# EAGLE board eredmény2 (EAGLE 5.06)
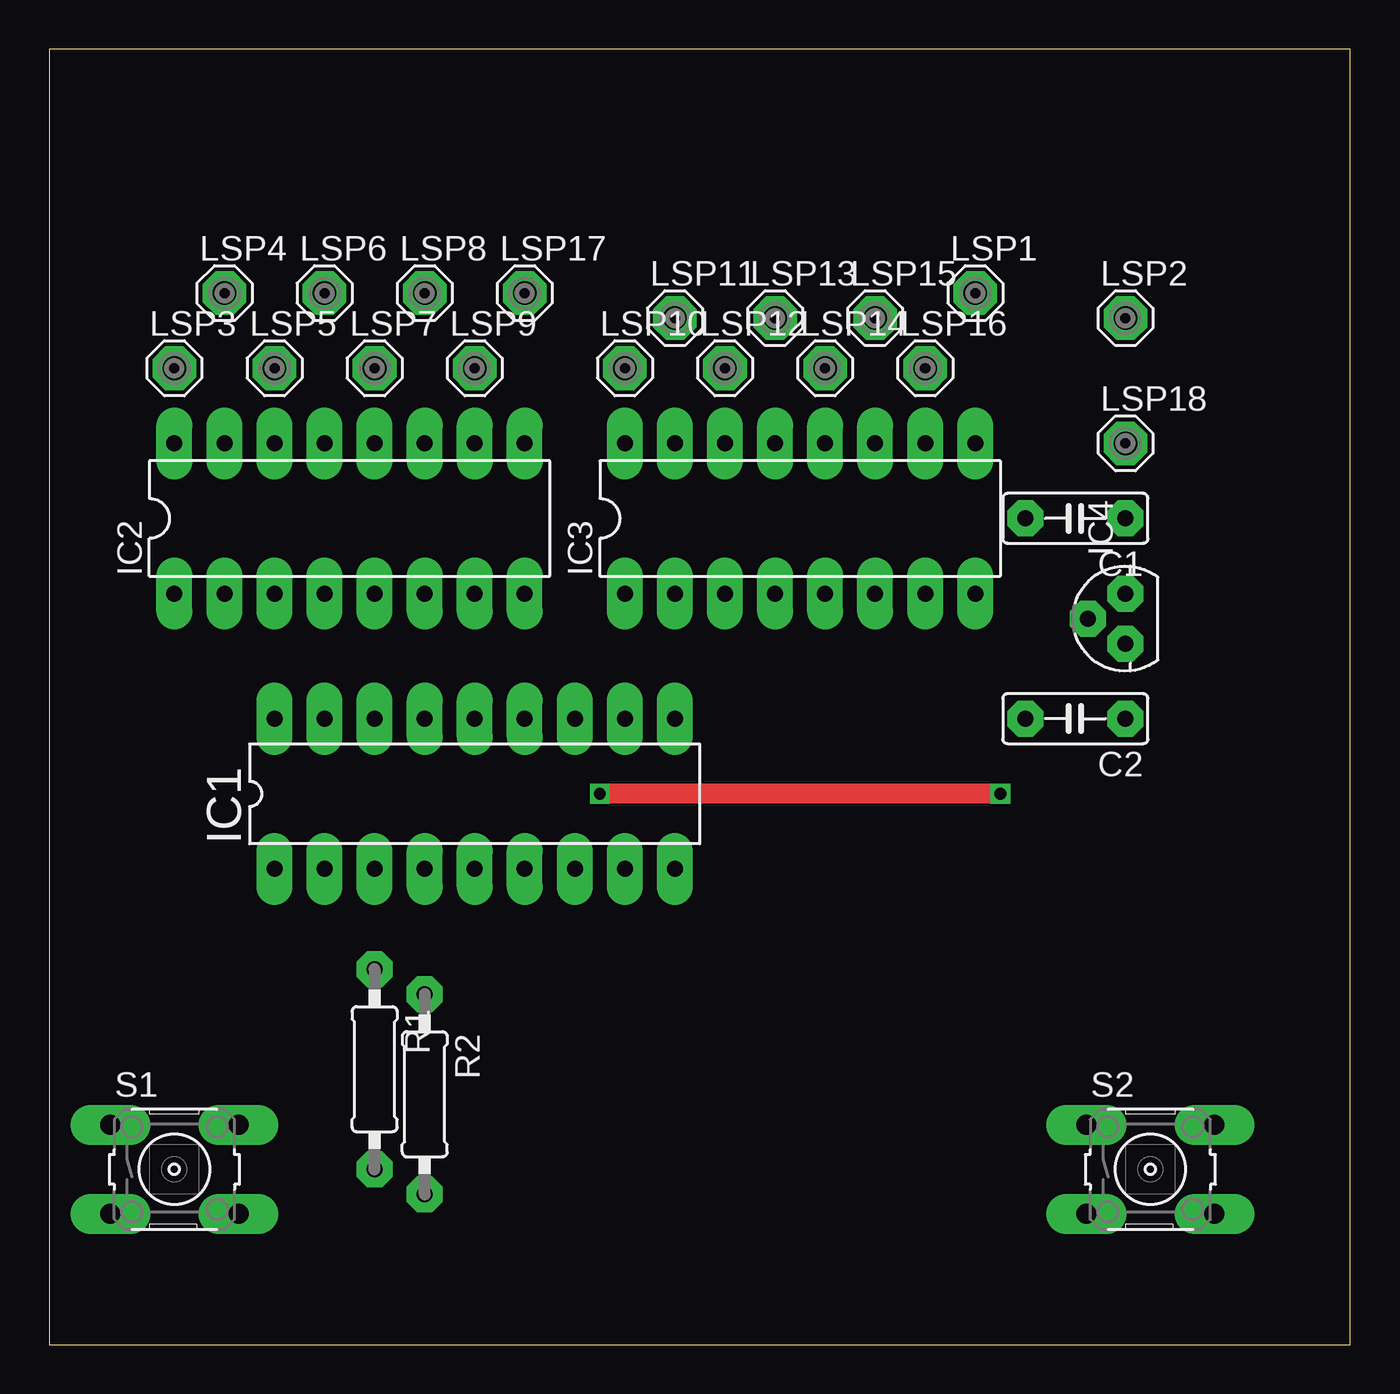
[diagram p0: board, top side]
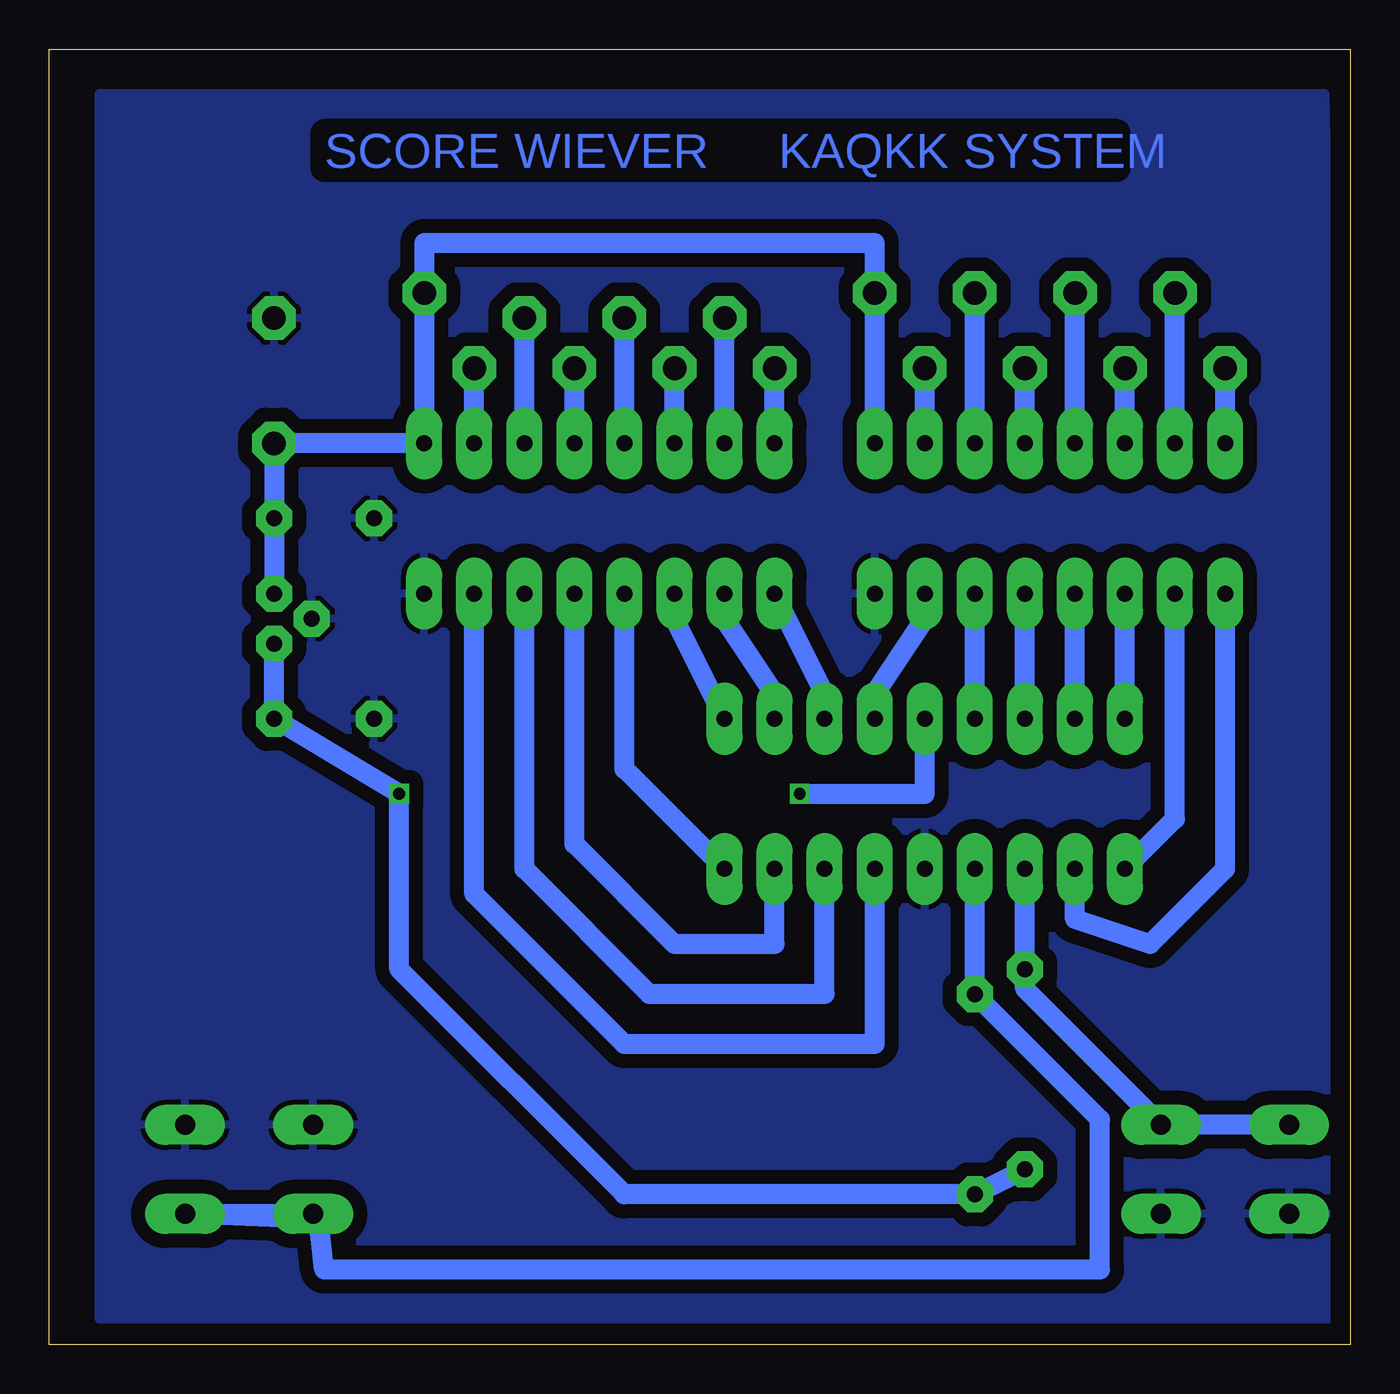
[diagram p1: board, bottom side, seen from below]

Size 66.02 x 65.71 mm. Coordinates in mm from the lower left corner, seen from the top.
Outline: 0,0 66.02,0 66.02,65.71 0,65.71 0,0
Copper layers (1*16): Top 0.035mm / dielectric 1.5mm / Bottom 0.035mm
Design rules "default *": minimum track width 10mil, minimum drill 24mil, track to track 28mil, track to pad 28mil, pad to pad 8mil, via to via 8mil, smd to smd 8mil, copper to edge 40mil, drill to drill 8mil, minimum pad ring 20mil, minimum via ring 8mil, stop-mask expansion 4mil, vias tented up to drill 0mil, thermal gap 10mil

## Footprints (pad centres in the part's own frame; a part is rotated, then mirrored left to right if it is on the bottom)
C050-025X075 = drill 0.813 octagon: 1 -2.54,0; 2 2.54,0
DIL18 = drill 0.813 long: 1 -10.16,-3.81; 2 -7.62,-3.81; 3 -5.08,-3.81; 4 -2.54,-3.81; 5 0,-3.81; 6 2.54,-3.81; 7 5.08,-3.81; 8 7.62,-3.81; 9 10.16,-3.81; 10 10.16,3.81; 11 7.62,3.81; 12 5.08,3.81; 13 2.54,3.81; 14 0,3.81; 15 -2.54,3.81; 16 -5.08,3.81; 17 -7.62,3.81; 18 -10.16,3.81
DIL16 = drill 0.813 long: 1 -8.89,-3.81; 2 -6.35,-3.81; 3 -3.81,-3.81; 4 -1.27,-3.81; 5 1.27,-3.81; 6 3.81,-3.81; 7 6.35,-3.81; 8 8.89,-3.81; 9 8.89,3.81; 10 6.35,3.81; 11 3.81,3.81; 12 1.27,3.81; 13 -1.27,3.81; 14 -3.81,3.81; 15 -6.35,3.81; 16 -8.89,3.81
78LXX = drill 0.813 octagon: GND 0,1.905; IN 1.27,0; OUT -1.27,0
MCS08 = drill 1.194 pad 2.159 octagon: MP 0,0
0207/10 = drill 0.813 octagon: 1 -5.08,0; 2 5.08,0
B3F-10XX = drill 1.016 long: 1 -3.251,2.261; 2 3.251,2.261; 3 -3.251,-2.261; 4 3.251,-2.261

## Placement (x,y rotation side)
C1  [C050-025X075]  52.07,41.91 180 top
C2  [C050-025X075]  52.07,31.75 180 top
IC1  PIC16F628P  [DIL18]  21.59,27.94 0 top
IC2  ULN2003AN  [DIL16]  15.24,41.91 0 top
IC3  ULN2003AN  [DIL16]  38.1,41.91 0 top
IC4  [78LXX]  54.61,36.83 90 top
LSP1  MCS08  [MCS08]  46.99,53.34 0 top
LSP2  MCS08  [MCS08]  54.61,52.07 0 top
LSP3  MCS08  [MCS08]  6.35,49.53 0 top
LSP4  MCS08  [MCS08]  8.89,53.34 0 top
LSP5  MCS08  [MCS08]  11.43,49.53 0 top
LSP6  MCS08  [MCS08]  13.97,53.34 0 top
LSP7  MCS08  [MCS08]  16.51,49.53 0 top
LSP8  MCS08  [MCS08]  19.05,53.34 0 top
LSP9  MCS08  [MCS08]  21.59,49.53 0 top
LSP10  MCS08  [MCS08]  29.21,49.53 0 top
LSP11  MCS08  [MCS08]  31.75,52.07 0 top
LSP12  MCS08  [MCS08]  34.29,49.53 0 top
LSP13  MCS08  [MCS08]  36.83,52.07 0 top
LSP14  MCS08  [MCS08]  39.37,49.53 0 top
LSP15  MCS08  [MCS08]  41.91,52.07 0 top
LSP16  MCS08  [MCS08]  44.45,49.53 0 top
LSP17  MCS08  [MCS08]  24.13,53.34 0 top
LSP18  MCS08  [MCS08]  54.61,45.72 0 top
R1  [0207/10]  16.51,13.97 270 top
R2  [0207/10]  19.05,12.7 270 top
S1  [B3F-10XX]  6.35,8.89 0 top
S2  [B3F-10XX]  55.88,8.89 0 top

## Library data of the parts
C1 C2 R1 R2 = rcl
IC1 = microchip
IC2 IC3 = uln-udn
IC4 = v-reg
LSP1-LSP18 = solpad
S1 S2 = switch-omron

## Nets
GND: C1.2 C2.2 IC1.5 IC2.8 IC3.8 IC4.GND LSP2.MP S1.3 S1.4 S2.1 S2.2
N$1: IC1.17 IC2.4
N$2: IC1.18 IC2.3
N$3: IC1.1 IC2.2
N$4: IC1.15 IC2.6
N$5: IC1.3 R1.1 S1.1 S1.2
N$6: IC1.4 R2.1 S2.3 S2.4
N$7: IC1.6 IC3.7
N$8: IC1.8 IC3.5
N$9: IC1.7 IC3.6
N$10: C2.1 IC1.14 IC4.OUT R1.2 R2.2
N$11: IC1.10 IC3.3
N$12: IC1.11 IC3.2
N$13: IC1.12 IC3.1
N$16: IC1.13 IC2.7
N$17: IC1.16 IC2.5
N$19: IC1.9 IC3.4
N$21: IC1.2 IC2.1
N$35: C1.1 IC2.9 IC3.9 IC4.IN LSP1.MP LSP17.MP LSP18.MP
N$36: IC3.10 LSP16.MP
N$37: IC3.11 LSP15.MP
N$38: IC3.12 LSP14.MP
N$39: IC3.13 LSP13.MP
N$40: IC3.14 LSP12.MP
N$41: IC3.15 LSP11.MP
N$42: IC3.16 LSP10.MP
N$44: IC2.10 LSP9.MP
N$45: IC2.11 LSP8.MP
N$46: IC2.12 LSP7.MP
N$47: IC2.13 LSP6.MP
N$48: IC2.14 LSP5.MP
N$49: IC2.15 LSP4.MP
N$50: IC2.16 LSP3.MP

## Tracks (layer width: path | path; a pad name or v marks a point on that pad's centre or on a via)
GND
  pour Bottom: 63.5,63.5 1.27,63.5 0,1.27 63.5,1.27
N$1
  Bottom 1.016: IC1.17 IC2.4
N$2
  Bottom 1.016: IC1.18 IC2.3
N$3
  Bottom 1.016: IC1.1 8.89,26.67 IC2.2
N$4
  Bottom 1.016: IC1.15 IC2.6
N$5
  Bottom 1.016: IC1.3 R1.1 16.51,18.06 S1.2 S1.1
N$6
  Bottom 1.016: IC1.4 R2.1 12.7,11.43 12.7,3.81 52.07,3.81 52.35,6.35 S2.4 S2.3
N$7
  Bottom 1.016: IC1.6 24.13,15.24 36.83,15.24 44.45,22.86 IC3.7
N$8
  Bottom 1.016: IC1.8 29.21,20.32 34.29,20.32 39.37,25.4 IC3.5
N$9
  Bottom 1.016: IC1.7 26.67,17.78 35.56,17.78 41.91,24.13 IC3.6
N$10  (via drill 0.6)
  Top 1.016: v48.26,27.94 v27.94,27.94
  Bottom 1.016: C2.1 IC4.OUT C2.1 | C2.1 v48.26,27.94 48.26,19.05 36.83,7.62 R2.2 R1.2 | v27.94,27.94 21.59,27.94 IC1.14
N$11
  Bottom 0.254: 34.29,36.83 IC3.3
  Bottom 1.016: IC1.10 34.29,36.83
N$12
  Bottom 0.254: IC1.11 29.21,33.02 | 31.75,36.83 IC3.2
  Bottom 1.016: 29.21,33.02 31.75,36.83
N$13
  Bottom 0.254: IC1.12 26.67,33.02
  Bottom 1.016: 26.67,33.02 IC3.1
N$16
  Bottom 0.254: IC1.13 24.13,33.02 | 21.59,36.83 IC2.7
  Bottom 1.016: 24.13,33.02 21.59,36.83
N$17
  Bottom 1.016: IC1.16 IC2.5
N$19
  Bottom 1.016: IC1.9 36.83,29.21 IC3.4
N$21
  Bottom 1.016: IC1.2 13.97,21.59 10.16,20.32 6.35,24.13 IC2.1
N$35
  Bottom 1.016: IC2.9 LSP17.MP 24.13,55.88 46.99,55.88 LSP1.MP IC3.9 LSP18.MP C1.1 IC4.IN
N$36
  Bottom 1.016: IC3.10 LSP16.MP
N$37
  Bottom 1.016: IC3.11 LSP15.MP
N$38
  Bottom 1.016: IC3.12 LSP14.MP
N$39
  Bottom 1.016: IC3.13 LSP13.MP
N$40
  Bottom 1.016: IC3.14 LSP12.MP
N$41
  Bottom 1.016: IC3.15 LSP11.MP
N$42
  Bottom 1.016: IC3.16 LSP10.MP
N$44
  Bottom 1.016: IC2.10 LSP9.MP
N$45
  Bottom 1.016: IC2.11 LSP8.MP
N$46
  Bottom 1.016: IC2.12 LSP7.MP
N$47
  Bottom 1.016: IC2.13 LSP6.MP
N$48
  Bottom 1.016: IC2.14 LSP5.MP
N$49
  Bottom 1.016: IC2.15 LSP4.MP
N$50
  Bottom 1.016: IC2.16 LSP3.MP

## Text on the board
Bottom: SCORE WIEVER KAQKK SYSTEM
